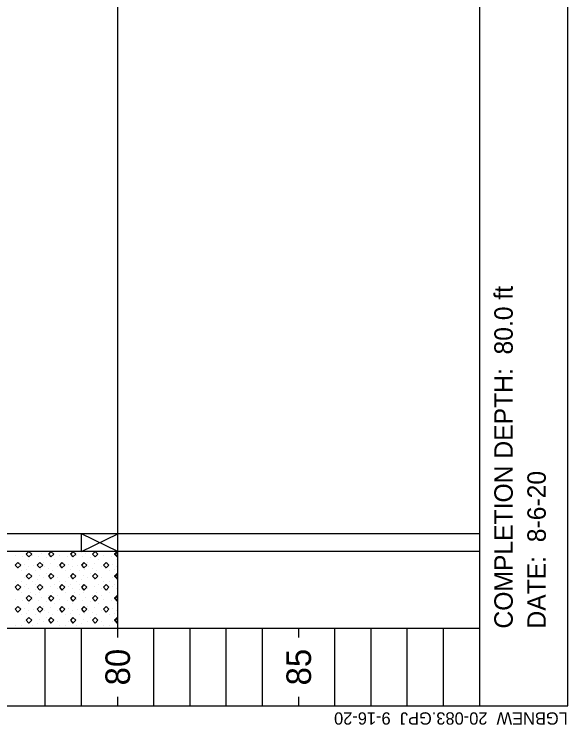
# Model space of a CAD drawing. Extents: x 1313964 to 1316843, y 2087046 to 2096619.
# Drawn here: x 1314219.61 to 1314234.9, y 2089927.64 to 2089947.25 of the extents above; entities that cross this region are included whole.
import ezdxf

# ---------------------------------------------------------------- set-up
doc = ezdxf.new("R2010")
doc.units = 0
doc.layers.add('B-Sub-Contour', color=7, linetype='Continuous')
doc.layers.add('Default', color=7, linetype='Continuous')

# ---------------------------------------------------------------- blocks, each defined once
blk = doc.blocks.new('POINT_DISPLAY')
at = {"layer": 'Default'}
blk.add_line((0, 0), (0, 0), dxfattribs=at)

msp = doc.modelspace()

# ---------------------------------------------------------------- linework, layer by layer
at = {"layer": 'B-Sub-Contour'}
for points in [[(1314234.904, 2089928.164), (1314234.904, 2089971.035), (1314173.485, 2089971.035), (1314173.485, 2089928.164), (1314234.904, 2089928.164)], [(1314232.471, 2089928.164), (1314232.471, 2089971.035)], [(1314222.471, 2089932.907), (1314222.471, 2089948.779)], [(1314232.471, 2089932.907), (1314187.471, 2089932.907)], [(1314221.471, 2089932.421), (1314222.471, 2089932.907)], [(1314222.471, 2089932.421), (1314221.471, 2089932.907)], [(1314221.471, 2089932.421), (1314221.471, 2089932.907)], [(1314222.471, 2089932.421), (1314222.471, 2089932.907)], [(1314222.471, 2089932.421), (1314222.471, 2089932.907)], [(1314232.471, 2089932.421), (1314180.782, 2089932.421)], [(1314222.471, 2089930.292), (1314222.471, 2089932.421)], [(1314232.471, 2089930.292), (1314180.782, 2089930.292)], [(1314220.471, 2089928.164), (1314220.471, 2089930.292)], [(1314220.471, 2089928.164), (1314220.471, 2089930.292)], [(1314221.471, 2089928.164), (1314221.471, 2089930.292)], [(1314222.471, 2089930.049), (1314222.471, 2089930.292)], [(1314222.471, 2089930.049), (1314222.471, 2089930.292)], [(1314223.471, 2089928.164), (1314223.471, 2089930.292)], [(1314224.471, 2089928.164), (1314224.471, 2089930.292)], [(1314224.471, 2089928.164), (1314224.471, 2089930.292)], [(1314225.471, 2089928.164), (1314225.471, 2089930.292)], [(1314226.471, 2089928.164), (1314226.471, 2089930.292)], [(1314226.471, 2089928.164), (1314226.471, 2089930.292)], [(1314227.471, 2089930.049), (1314227.471, 2089930.292)], [(1314228.471, 2089928.164), (1314228.471, 2089930.292)], [(1314228.471, 2089928.164), (1314228.471, 2089930.292)], [(1314229.471, 2089928.164), (1314229.471, 2089930.292)], [(1314230.471, 2089928.164), (1314230.471, 2089930.292)], [(1314230.471, 2089928.164), (1314230.471, 2089930.292)], [(1314231.471, 2089928.164), (1314231.471, 2089930.292)], [(1314232.471, 2089930.049), (1314232.471, 2089930.292)], [(1314232.471, 2089930.049), (1314232.471, 2089930.292)], [(1314222.471, 2089928.164), (1314222.471, 2089928.407)], [(1314222.471, 2089928.164), (1314222.471, 2089928.407)], [(1314227.471, 2089928.164), (1314227.471, 2089928.407)], [(1314232.471, 2089928.164), (1314232.471, 2089928.407)], [(1314232.471, 2089928.164), (1314232.471, 2089928.407)]]:
    msp.add_lwpolyline(points, dxfattribs=at)
for points in [[(1314220.021, 2089932.421), (1314219.948, 2089932.348), (1314220.021, 2089932.269), (1314220.1, 2089932.348)], [(1314220.629, 2089932.421), (1314220.556, 2089932.348), (1314220.629, 2089932.269), (1314220.708, 2089932.348)], [(1314221.237, 2089932.421), (1314221.164, 2089932.348), (1314221.237, 2089932.269), (1314221.316, 2089932.348)], [(1314221.845, 2089932.421), (1314221.772, 2089932.348), (1314221.845, 2089932.269), (1314221.924, 2089932.348)], [(1314222.471, 2089932.404), (1314222.452, 2089932.421), (1314222.38, 2089932.348), (1314222.471, 2089932.404)], [(1314222.471, 2089932.287), (1314222.471, 2089932.404), (1314222.38, 2089932.348), (1314222.471, 2089932.287)], [(1314222.453, 2089932.269), (1314222.471, 2089932.287), (1314222.38, 2089932.348), (1314222.453, 2089932.269)], [(1314222.471, 2089932.404), (1314222.454, 2089932.421), (1314222.452, 2089932.421), (1314222.471, 2089932.404)], [(1314219.716, 2089932.117), (1314219.644, 2089932.044), (1314219.716, 2089931.965), (1314219.796, 2089932.044)], [(1314220.325, 2089932.117), (1314220.252, 2089932.044), (1314220.325, 2089931.965), (1314220.404, 2089932.044)], [(1314220.933, 2089932.117), (1314220.86, 2089932.044), (1314220.933, 2089931.965), (1314221.012, 2089932.044)], [(1314221.541, 2089932.117), (1314221.468, 2089932.044), (1314221.541, 2089931.965), (1314221.62, 2089932.044)], [(1314222.149, 2089932.117), (1314222.076, 2089932.044), (1314222.149, 2089931.965), (1314222.228, 2089932.044)], [(1314220.021, 2089931.813), (1314219.948, 2089931.74), (1314220.021, 2089931.661), (1314220.1, 2089931.74)], [(1314220.629, 2089931.813), (1314220.556, 2089931.74), (1314220.629, 2089931.661), (1314220.708, 2089931.74)], [(1314221.237, 2089931.813), (1314221.164, 2089931.74), (1314221.237, 2089931.661), (1314221.316, 2089931.74)], [(1314221.845, 2089931.813), (1314221.772, 2089931.74), (1314221.845, 2089931.661), (1314221.924, 2089931.74)], [(1314222.471, 2089931.796), (1314222.453, 2089931.813), (1314222.38, 2089931.74), (1314222.471, 2089931.796)], [(1314222.471, 2089931.679), (1314222.471, 2089931.796), (1314222.38, 2089931.74), (1314222.471, 2089931.679)], [(1314222.453, 2089931.661), (1314222.471, 2089931.679), (1314222.38, 2089931.74), (1314222.453, 2089931.661)], [(1314219.716, 2089931.508), (1314219.644, 2089931.436), (1314219.716, 2089931.356), (1314219.796, 2089931.436)], [(1314220.325, 2089931.508), (1314220.252, 2089931.436), (1314220.325, 2089931.356), (1314220.404, 2089931.436)], [(1314220.933, 2089931.508), (1314220.86, 2089931.436), (1314220.933, 2089931.356), (1314221.012, 2089931.436)], [(1314221.541, 2089931.508), (1314221.468, 2089931.436), (1314221.541, 2089931.356), (1314221.62, 2089931.436)], [(1314222.149, 2089931.508), (1314222.076, 2089931.436), (1314222.149, 2089931.356), (1314222.228, 2089931.436)], [(1314220.021, 2089931.204), (1314219.948, 2089931.131), (1314220.021, 2089931.052), (1314220.1, 2089931.131)], [(1314220.629, 2089931.204), (1314220.556, 2089931.131), (1314220.629, 2089931.052), (1314220.708, 2089931.131)], [(1314221.237, 2089931.204), (1314221.164, 2089931.131), (1314221.237, 2089931.052), (1314221.316, 2089931.131)], [(1314221.845, 2089931.204), (1314221.772, 2089931.131), (1314221.845, 2089931.052), (1314221.924, 2089931.131)], [(1314222.471, 2089931.188), (1314222.453, 2089931.204), (1314222.38, 2089931.131), (1314222.471, 2089931.188)], [(1314222.471, 2089931.071), (1314222.471, 2089931.188), (1314222.38, 2089931.131), (1314222.471, 2089931.071)], [(1314222.453, 2089931.052), (1314222.471, 2089931.071), (1314222.38, 2089931.131), (1314222.453, 2089931.052)], [(1314219.716, 2089930.9), (1314219.644, 2089930.827), (1314219.716, 2089930.748), (1314219.796, 2089930.827)], [(1314220.325, 2089930.9), (1314220.252, 2089930.827), (1314220.325, 2089930.748), (1314220.404, 2089930.827)], [(1314220.933, 2089930.9), (1314220.86, 2089930.827), (1314220.933, 2089930.748), (1314221.012, 2089930.827)], [(1314221.541, 2089930.9), (1314221.468, 2089930.827), (1314221.541, 2089930.748), (1314221.62, 2089930.827)], [(1314222.149, 2089930.9), (1314222.076, 2089930.827), (1314222.149, 2089930.748), (1314222.228, 2089930.827)], [(1314220.021, 2089930.596), (1314219.948, 2089930.523), (1314220.021, 2089930.444), (1314220.1, 2089930.523)], [(1314220.629, 2089930.596), (1314220.556, 2089930.523), (1314220.629, 2089930.444), (1314220.708, 2089930.523)], [(1314221.237, 2089930.596), (1314221.164, 2089930.523), (1314221.237, 2089930.444), (1314221.316, 2089930.523)], [(1314221.845, 2089930.596), (1314221.772, 2089930.523), (1314221.845, 2089930.444), (1314221.924, 2089930.523)], [(1314222.471, 2089930.579), (1314222.453, 2089930.596), (1314222.38, 2089930.523), (1314222.471, 2089930.579)], [(1314222.471, 2089930.463), (1314222.471, 2089930.579), (1314222.38, 2089930.523), (1314222.471, 2089930.463)], [(1314222.453, 2089930.444), (1314222.471, 2089930.463), (1314222.38, 2089930.523), (1314222.453, 2089930.444)]]:
    msp.add_lwpolyline(points, close=True, dxfattribs=at)

# ---------------------------------------------------------------- block references
at = {"layer": 'B-Sub-Contour', "xscale": 0.019951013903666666, "yscale": 0.019951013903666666, "rotation": 90}
for p in [(1314219.644, 2089932.31), (1314219.948, 2089932.37), (1314220.13, 2089932.31), (1314220.373, 2089932.37), (1314220.616, 2089932.31), (1314220.86, 2089932.31), (1314221.164, 2089932.37), (1314221.346, 2089932.31), (1314221.589, 2089932.37), (1314221.833, 2089932.31), (1314222.076, 2089932.31), (1314222.38, 2089932.37), (1314219.765, 2089932.127), (1314219.856, 2089932.285), (1314220.008, 2089932.188), (1314220.285, 2089932.282), (1314220.434, 2089932.127), (1314220.495, 2089932.249), (1314220.738, 2089932.188), (1314220.981, 2089932.127), (1314221.073, 2089932.285), (1314221.225, 2089932.188), (1314221.501, 2089932.282), (1314221.65, 2089932.127), (1314221.711, 2089932.249), (1314221.954, 2089932.188), (1314222.198, 2089932.127), (1314222.289, 2089932.285), (1314222.441, 2089932.188), (1314219.704, 2089931.945), (1314219.887, 2089932.066), (1314219.942, 2089931.926), (1314220.008, 2089932.006), (1314220.147, 2089932.036), (1314220.252, 2089932.066), (1314220.332, 2089931.918), (1314220.459, 2089932.011), (1314220.556, 2089931.945), (1314220.616, 2089932.089), (1314220.799, 2089932.006), (1314220.921, 2089931.945), (1314221.103, 2089932.066), (1314221.158, 2089931.926), (1314221.225, 2089932.006), (1314221.363, 2089932.036), (1314221.468, 2089932.066), (1314221.548, 2089931.918), (1314221.675, 2089932.011), (1314221.772, 2089931.945), (1314221.833, 2089932.089), (1314222.015, 2089932.006), (1314222.137, 2089931.945), (1314222.319, 2089932.066), (1314222.374, 2089931.926), (1314222.441, 2089932.006), (1314219.826, 2089931.884), (1314220.069, 2089931.762), (1314220.191, 2089931.884), (1314220.312, 2089931.762), (1314220.495, 2089931.823), (1314220.677, 2089931.884), (1314221.042, 2089931.884), (1314221.285, 2089931.762), (1314221.407, 2089931.884), (1314221.529, 2089931.762), (1314221.711, 2089931.823), (1314221.894, 2089931.884), (1314222.258, 2089931.884), (1314219.644, 2089931.58), (1314219.826, 2089931.58), (1314219.887, 2089931.702), (1314219.948, 2089931.519), (1314220.008, 2089931.641), (1314220.13, 2089931.58), (1314220.252, 2089931.641), (1314220.373, 2089931.519), (1314220.434, 2089931.702), (1314220.616, 2089931.641), (1314220.738, 2089931.519), (1314220.799, 2089931.702), (1314220.86, 2089931.58), (1314221.042, 2089931.58), (1314221.103, 2089931.702), (1314221.164, 2089931.519), (1314221.225, 2089931.641), (1314221.346, 2089931.58), (1314221.468, 2089931.641), (1314221.589, 2089931.519), (1314221.65, 2089931.702), (1314221.833, 2089931.641), (1314221.954, 2089931.519), (1314222.015, 2089931.702), (1314222.076, 2089931.58), (1314222.258, 2089931.58), (1314222.319, 2089931.702), (1314222.38, 2089931.519), (1314222.441, 2089931.641), (1314219.704, 2089931.505), (1314219.765, 2089931.337), (1314219.887, 2089931.458), (1314220.008, 2089931.398), (1314220.191, 2089931.498), (1314220.207, 2089931.378), (1314220.312, 2089931.458), (1314220.434, 2089931.398), (1314220.603, 2089931.441), (1314220.799, 2089931.398), (1314220.921, 2089931.505), (1314220.981, 2089931.337), (1314221.103, 2089931.458), (1314221.225, 2089931.398), (1314221.407, 2089931.498), (1314221.424, 2089931.378), (1314221.529, 2089931.458), (1314221.65, 2089931.398), (1314221.819, 2089931.441), (1314222.015, 2089931.398), (1314222.137, 2089931.505), (1314222.198, 2089931.337), (1314222.319, 2089931.458), (1314222.441, 2089931.398), (1314219.826, 2089931.276), (1314219.948, 2089931.154), (1314220.069, 2089931.276), (1314220.199, 2089931.231), (1314220.312, 2089931.276), (1314220.373, 2089931.154), (1314220.556, 2089931.215), (1314220.677, 2089931.276), (1314220.799, 2089931.218), (1314221.042, 2089931.276), (1314221.164, 2089931.154), (1314221.285, 2089931.276), (1314221.415, 2089931.231), (1314221.529, 2089931.276), (1314221.589, 2089931.154), (1314221.772, 2089931.215), (1314221.894, 2089931.276), (1314222.015, 2089931.218), (1314222.258, 2089931.276), (1314222.38, 2089931.154), (1314219.644, 2089931.093), (1314219.856, 2089931.069), (1314220.008, 2089930.972), (1314220.13, 2089931.093), (1314220.285, 2089931.066), (1314220.495, 2089931.033), (1314220.616, 2089931.093), (1314220.738, 2089930.972), (1314220.86, 2089931.093), (1314221.073, 2089931.069), (1314221.225, 2089930.972), (1314221.346, 2089931.093), (1314221.501, 2089931.066), (1314221.711, 2089931.033), (1314221.833, 2089931.093), (1314221.954, 2089930.972), (1314222.076, 2089931.093), (1314222.289, 2089931.069), (1314222.441, 2089930.972), (1314219.704, 2089930.729), (1314219.765, 2089930.911), (1314219.887, 2089930.85), (1314220.008, 2089930.789), (1314220.147, 2089930.82), (1314220.252, 2089930.85), (1314220.434, 2089930.911), (1314220.459, 2089930.795), (1314220.556, 2089930.729), (1314220.616, 2089930.873), (1314220.799, 2089930.789), (1314220.921, 2089930.729), (1314220.981, 2089930.911), (1314221.103, 2089930.85), (1314221.225, 2089930.789), (1314221.363, 2089930.82), (1314221.468, 2089930.85), (1314221.65, 2089930.911), (1314221.675, 2089930.795), (1314221.772, 2089930.729), (1314221.833, 2089930.873), (1314222.015, 2089930.789), (1314222.137, 2089930.729), (1314222.198, 2089930.911), (1314222.319, 2089930.85), (1314222.441, 2089930.789), (1314219.826, 2089930.668), (1314219.942, 2089930.71), (1314220.069, 2089930.546), (1314220.191, 2089930.668), (1314220.312, 2089930.546), (1314220.332, 2089930.701), (1314220.495, 2089930.607), (1314220.677, 2089930.668), (1314221.042, 2089930.668), (1314221.158, 2089930.71), (1314221.285, 2089930.546), (1314221.407, 2089930.668), (1314221.529, 2089930.546), (1314221.548, 2089930.701), (1314221.711, 2089930.607), (1314221.894, 2089930.668), (1314222.258, 2089930.668), (1314222.374, 2089930.71), (1314219.644, 2089930.364), (1314219.826, 2089930.364), (1314219.887, 2089930.485), (1314220.008, 2089930.425), (1314220.13, 2089930.364), (1314220.252, 2089930.425), (1314220.434, 2089930.485), (1314220.616, 2089930.425), (1314220.799, 2089930.485), (1314220.86, 2089930.364), (1314221.042, 2089930.364), (1314221.103, 2089930.485), (1314221.225, 2089930.425), (1314221.346, 2089930.364), (1314221.468, 2089930.425), (1314221.65, 2089930.485), (1314221.833, 2089930.425), (1314222.015, 2089930.485), (1314222.076, 2089930.364), (1314222.258, 2089930.364), (1314222.319, 2089930.485), (1314222.441, 2089930.425), (1314219.948, 2089930.303), (1314220.373, 2089930.303), (1314220.738, 2089930.303), (1314221.164, 2089930.303), (1314221.589, 2089930.303), (1314221.954, 2089930.303), (1314222.38, 2089930.303)]:
    msp.add_blockref('POINT_DISPLAY', p, dxfattribs=at)

# ---------------------------------------------------------------- texts
at = {"layer": 'B-Sub-Contour'}
for s, height, rotation, p in [('COMPLETION DEPTH:  80.0 ft', 0.50899, 90, (1314233.383, 2089930.292)), ('DATE:  8-6-20', 0.50899, 90, (1314234.296, 2089930.292)), ('80', 0.6786, 90, (1314222.811, 2089928.724)), ('80', 0.6786, 90, (1314222.811, 2089928.724)), ('85', 0.6786, 90, (1314227.811, 2089928.724)), ('LGBNEW  20-083.GPJ  9-16-20', 0.33932, 180, (1314234.904, 2089927.981))]:
    msp.add_text(s, height=height, rotation=rotation, dxfattribs=at).set_placement(p)

doc.saveas('drawing.dxf')
